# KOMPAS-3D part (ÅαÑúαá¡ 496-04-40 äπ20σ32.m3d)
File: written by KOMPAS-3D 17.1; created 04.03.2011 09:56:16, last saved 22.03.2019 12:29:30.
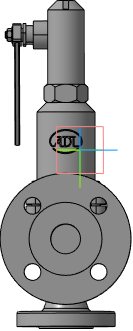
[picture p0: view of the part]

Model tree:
1. Плоскость XY
2. Плоскость ZX
3. Плоскость ZY
4. Ось X
5. Ось Y
6. Ось Z
7. Начало координат
8. Операция без истории:2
